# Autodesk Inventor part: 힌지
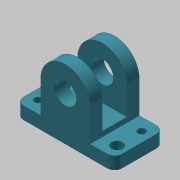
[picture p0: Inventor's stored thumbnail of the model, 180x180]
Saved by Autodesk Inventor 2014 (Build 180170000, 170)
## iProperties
Created: 2019-09
Part Number: 힌지
Material: 알루미늄 6061
Document SubType Name: Modeling
Designer: mduedu
Density: 2.71 g/cm^3
Appearance: 커뎃 파란색
Mass: 20.7756 g
Surface Area: 43.3328 cm^2
Volume: 7.66627 cm^3
Author: mduedu
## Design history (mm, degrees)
sketch "스케치1"
  geometry: L1 (-20, 0)-(20, 0); L2 (20, 0)-(20, 5); L3 (-20, 5)-(-20, 0); L4 (10, 5)-(10, 18); L5 (-10, 18)-(-10, 5); L6 (20, 5)-(10, 5); L7 (-10, 5)-(-20, 5); C1 r 4.5 at (0, 18); A1 r 10 centre (0, 18) between (10, 18) and (-10, 18); 2 further points
  constraints: 14 end point, 4 parallel, 2 centre point, 2 coincident, 2 point on circle, 2 tangent, 1 collinear, 1 horizontal, 1 midpoint, 1 perpendicular, 1 vertical, 1 vertical alignment
  dimensions: "d0" = 40 distance of L1.start L1.end; "d2" = 20 distance between parallel lines of L4 L5; "d3" = 18 distance from line of L1 A1.centre; "d4" = 5 distance of L1.end L2.end; "d5" = 9 diameter of C1
extrude "돌출1" new body sketch "스케치1" stored distance "d6" = 20; taper "d7" = 0 deg
sketch "스케치2"
  geometry: L1 (7, 5)-(37, 5); L2 (37, 5)-(37, -5); L3 (37, -5)-(7, -5); L4 (7, -5)-(7, 5); L5 (0, 10)-(0, -10) reference; 2 further points
  constraints: 8 end point, 2 parallel, 1 horizontal, 1 horizontal alignment, 1 midpoint, 1 perpendicular
  dimensions: "d8" = 7 distance between parallel lines of L5 L4; "d9" = 10 distance of L1.end L2.end; "d10" = 30 distance of L2.end L3.end
extrude "돌출2" cut sketch "스케치2" stored distance "d11" = 20; taper "d12" = 0 deg
sketch "스케치3"
  geometry: 3 further points
  dimensions: "d13" = 16 horizontal distance of point (6, 15) point (-10, 10); "d14" = 32 horizontal distance of point (-26, 5) point (6, 15); "d15" = 5 vertical distance of point (6, 15) point (-10, 10); "d16" = 10 vertical distance of point (-26, 5) point (6, 15)
hole "구멍1" sketch "스케치3" at (6, 15), (-26, 5) diameter "d17" = 3; stored, may be unused: countersink angle "d21" = 90 deg, drill point angle "d23" = 118 deg; dims "d18" = 6, "d19" = 4, "d20" = 2, "d22" = 8
sketch "스케치4"
  geometry: C1 r 1.5 at (6, 15) reference; C2 r 1.5 at (-26, 5) reference; 3 further points
  constraints: 2 horizontal alignment, 2 vertical alignment
hole "구멍2" sketch "스케치4" at (-26, 15), (6, 5) diameter "d24" = 4.5; stored, may be unused: countersink angle "d28" = 90 deg, drill point angle "d30" = 118 deg; dims "d25" = 6, "d26" = 4, "d27" = 2, "d29" = 8
fillet "모깎기1" dims "d31" = 3
node "솔리드1"
